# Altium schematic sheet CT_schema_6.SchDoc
size 308 x 301 mm
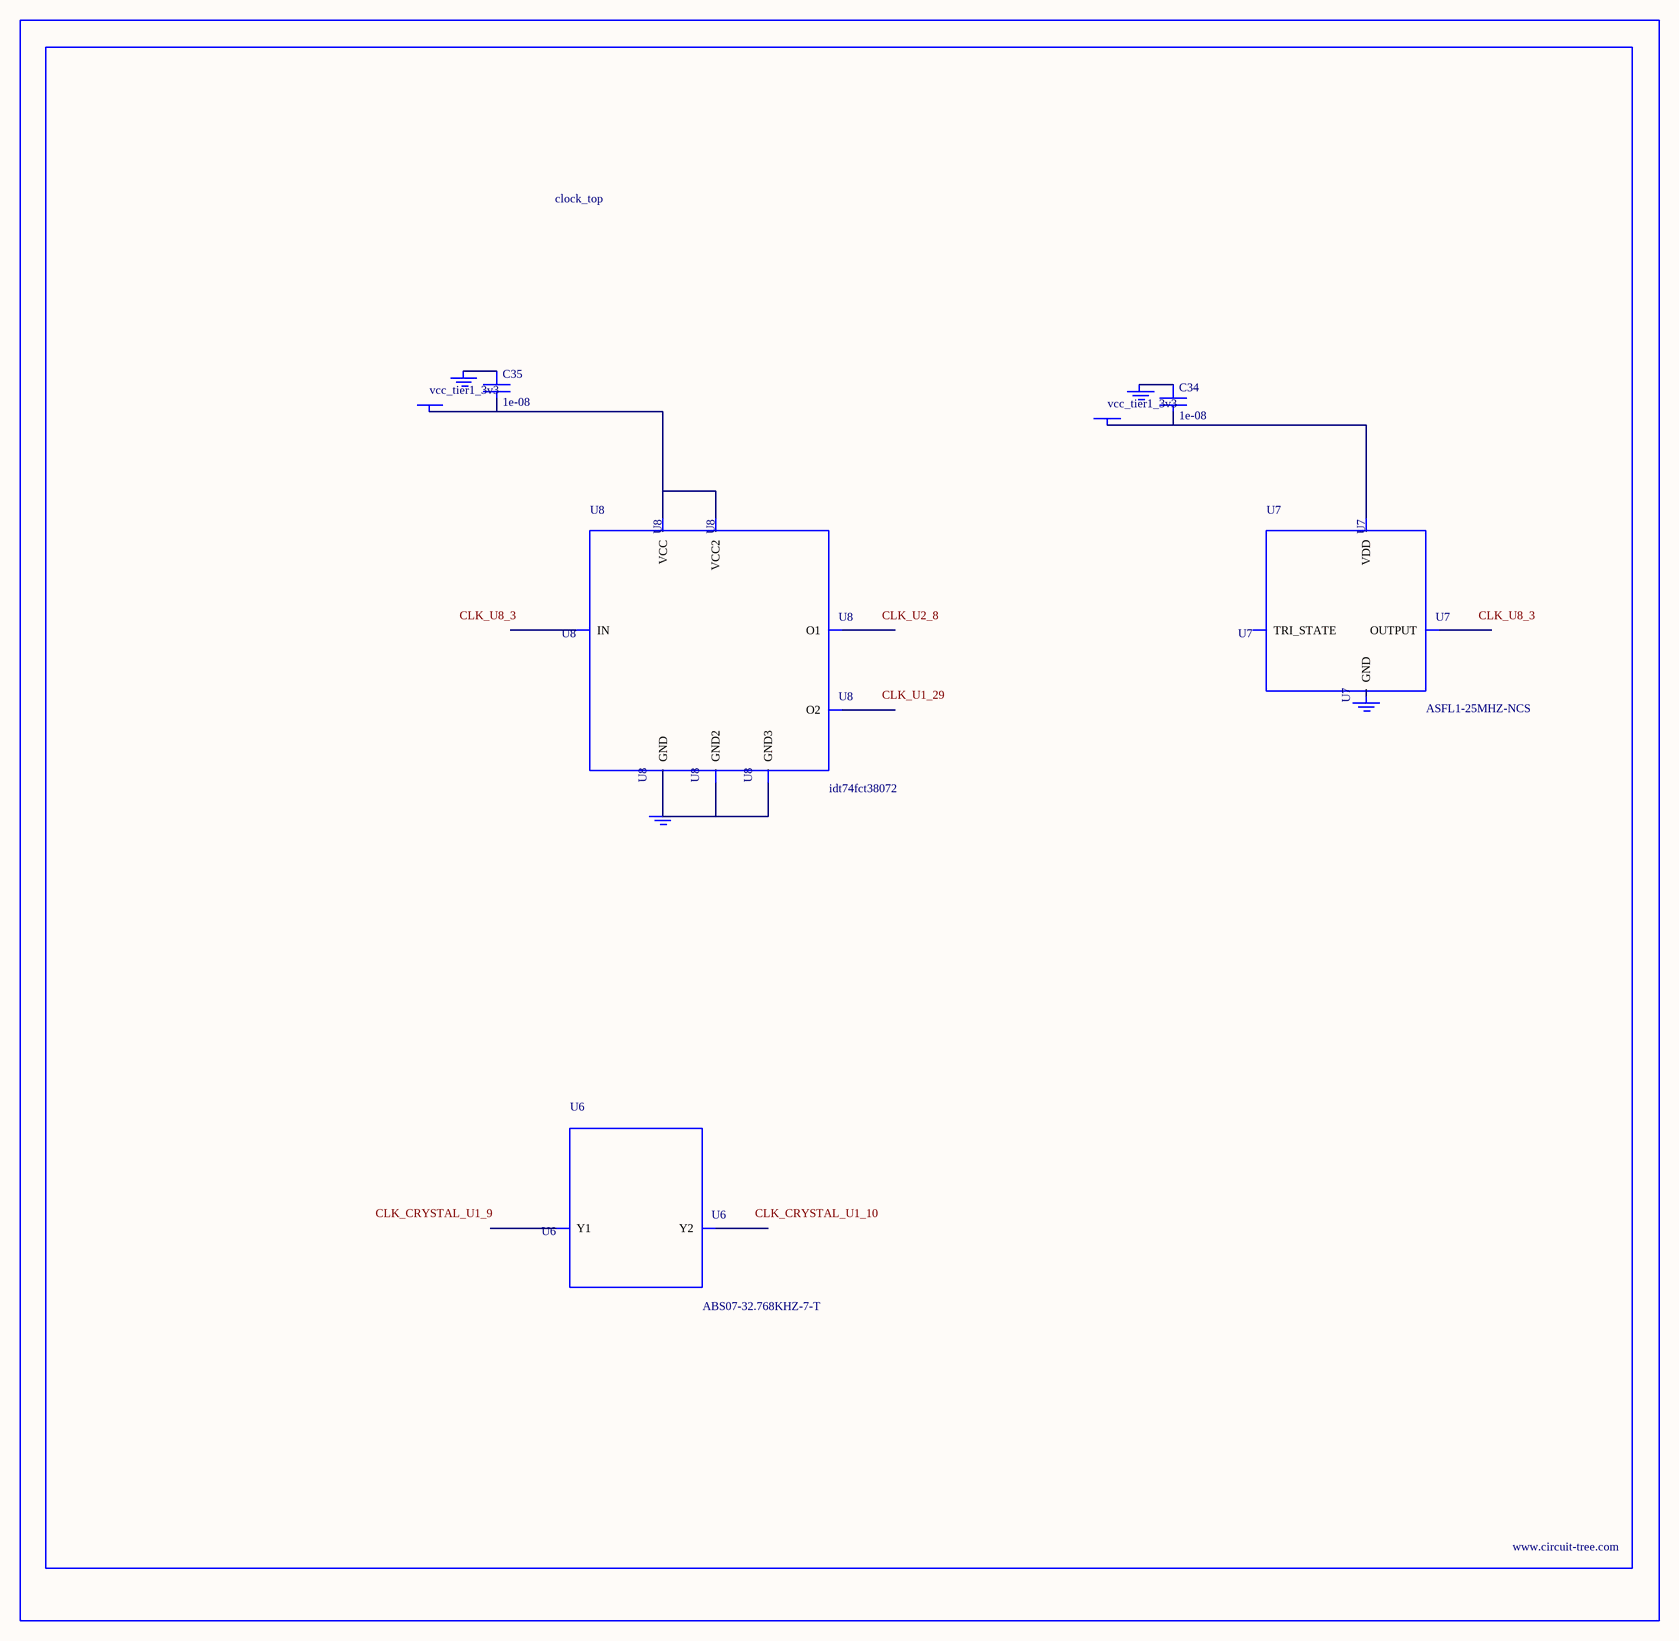
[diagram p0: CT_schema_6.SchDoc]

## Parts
BORDER5  (no value)
C34  1e-08  [C0402]
C35  1e-08  [C0402]
GND_INSTANCE_5_0  (no value)
GND_INSTANCE_5_1  (no value)
GND_INSTANCE_5_2  (no value)
GND_INSTANCE_5_3  (no value)
POWER_INSTANCE_5_0  vcc_tier1_3v3
POWER_INSTANCE_5_1  vcc_tier1_3v3
U6  ABS07-32.768KHZ-7-T  [ABS07-32.768KHZ-7-T]
U7  ASFL1-25MHZ-NCS  [ASFL1]
U8  idt74fct38072  [IDT74FCT38072]

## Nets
NetC34_1: C34.1 GND_INSTANCE_5_0.0(GND)
NetC34_2: C34.2 POWER_INSTANCE_5_0.0(PWR) U7.4(VDD)
NetC35_1: C35.1 GND_INSTANCE_5_2.0(GND)
NetC35_2: C35.2 POWER_INSTANCE_5_1.0(PWR) U8.1(VCC) U8.2(VCC2)
NetGND_INSTANCE_5_3_0: GND_INSTANCE_5_3.0(GND) U8.4(GND) U8.5(GND2) U8.8(GND3)

Not connected (* = marked no-connect by the designer): GND_INSTANCE_5_1 0(GND); U6 1(Y1) 2(Y2); U7 1(TRI_STATE) 2(GND) 3(OUTPUT); U8 3(IN) 6(O2) 7(O1)

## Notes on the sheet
- Labels drawn without touching a wire or pin: CLK_CRYSTAL_U1_9, CLK_CRYSTAL_U1_10, CLK_U1_29, CLK_U2_8, CLK_U8_3

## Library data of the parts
BORDER5 = BORDER_PAGE5
C34 C35 = C0402C103K3RAC
GND_INSTANCE_5_0-GND_INSTANCE_5_3 = GND
POWER_INSTANCE_5_0 POWER_INSTANCE_5_1 = PWR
